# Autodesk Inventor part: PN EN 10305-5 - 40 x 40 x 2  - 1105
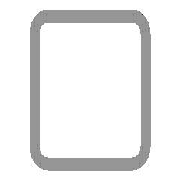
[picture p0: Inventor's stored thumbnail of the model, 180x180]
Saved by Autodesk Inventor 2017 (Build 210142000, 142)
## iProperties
_CCFamilyMember: 26
_CCFamilyDisplayName: PN EN 10305-5 (Rury kwadratowe, spawane, wymiarowane na zimno) - Rury stalowe do zastosowań precyzyjnych -  (Część 5: Rury kwadratowe, spawane, wymiarowane na z
_FrameMemberDoc: Frame Member File
_Version: 15.0.0
_GetPNFromCC: 1
Created: 2016-02
Part Number: PN EN 10305-5 - 40 x 40 x 2  - 1105
Material: Stal, miękka
Description: Rury stalowe do zastosowań precyzyjnych -  (Część 5: Rury kwadratowe, spawane, wymiarowane na zimno)
Document SubType Name: Modeling
Standard: PN
Designer: X
Standards Organization: PN
Language: pl-PL
Size Designation: 40 x 40 x 2
Categories: <MemberInstance><Categories><Category DisplayName="Kształtowniki konstrukcyjne" InternalName="089c4875-fa83-4c05-b084-43b9cc11f5ed" Mnemonic="GRDR"><CategoryPar
Stock Number: 40 x 40 x 2
Density: 7.85 g/cm^3
Appearance: Częściowo polerowana
Mass: 2577.4 g
Surface Area: 3289.26 cm^2
Volume: 328.332 cm^3
IsCustomPart: 1
G_L: 1105,000 mm
G_W: 40,000 mm
G_H: 40,000 mm
Author: X
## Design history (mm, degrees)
node "Płaszczyzna początkowa"
node "Płaszczyzna końcowa"
sketch "Szkic"
  geometry: L1 (-20, -17)-(-20, 17); L2 (-17, 20)-(17, 20); L3 (20, 17)-(20, -17); L4 (17, -20)-(-17, -20); L5 (-17, 18)-(17, 18); L6 (18, 17)-(18, -17); L7 (17, -18)-(-17, -18); L8 (-18, -17)-(-18, 17); L9 (0, 25.37)-(0, -25.37) reference; L10 (-25.37, 0)-(25.37, 0) reference; A1 r 3 centre (-17, -17) between (-20, -17) and (-17, -20); A2 r 3 centre (-17, 17) between (-17, 20) and (-20, 17); A3 r 3 centre (17, 17) between (20, 17) and (17, 20); A4 r 3 centre (17, -17) between (17, -20) and (20, -17); A5 r 1 centre (-17, 17) between (-17, 18) and (-18, 17); A6 r 1 centre (17, 17) between (18, 17) and (17, 18); A7 r 1 centre (17, -17) between (17, -18) and (18, -17); A8 r 1 centre (-17, -17) between (-18, -17) and (-17, -18)
  constraints: 16 end point, 16 point on circle, 8 centre point, 8 tangent, 4 parallel, 3 equal radius, 2 perpendicular, 7 other
  dimensions: "d7" = 3 radius of A1 (= G_IR); "d10" = 40 distance between parallel lines of L2 L4 (= G_H); "d11" = 40 distance between parallel lines of L1 L3 (= G_W); "d12" = 2 distance between parallel lines of L3 L6 (= G_T); "d15" = 20 distance between parallel lines of L2 L10 (= 0.5 x d10); "d16" = 20 distance between parallel lines of L9 L3 (= 0.5 x d11)
extrude "Bryła" new body sketch "Szkic" stored distance "d3" = 1105 (= G_L); taper "d4" = 0 deg
node "Driven Length"
  sketch "Sketch3"
    geometry: L1 (0, 0)-(10, 0) reference
    constraints: 2 end point, 1 horizontal
  workplane "Work Plane3"
  sketch "Sketch4"
    geometry: L1 (-2, 0)-(12, 0) reference; L2 (-2, 1105)-(12, 1105) reference
    dimensions: "d18" = 1105 distance between parallel lines of L1 L2 (derived)
body "Solid1"
other parameters: "G_W" = 40 [user parameter; used in 1 equation term], "G_H" = 40 [user parameter; used in 1 equation term], "G_T" = 2 [user parameter; used in 1 equation term], "G_IR" = 3 [user parameter; used in 1 equation term], "G_L" = 1105 (= d18) [user parameter; used in 1 equation term], "G_OFFSET_START" = 0 [user parameter; used in 1 equation term], "G_OFFSET_END" = -35 [user parameter; used in 1 equation term], "d13" = 0 (computed from G_OFFSET_START), "d14" = 1105 (= G_OFFSET_END + B_L), "d17" = 90 deg
